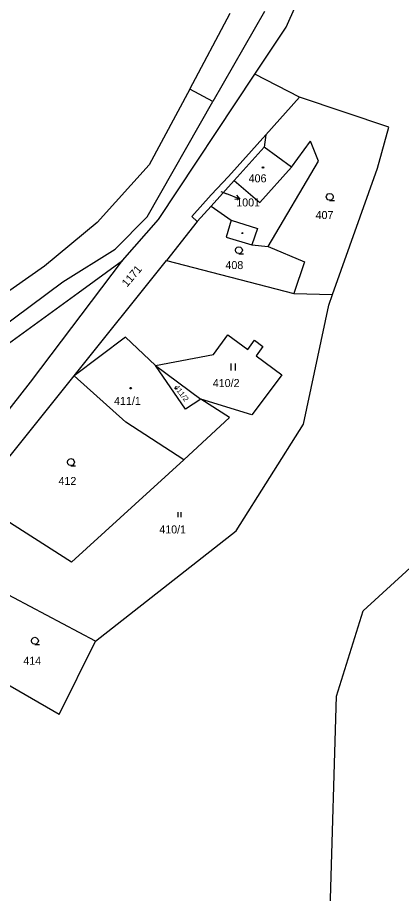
# Model space of a CAD drawing. Extents: x -812394 to -807601, y -1013097 to -1009266.
# Drawn here: x -810837.2 to -810755.5, y -1011724.6 to -1011538.5 of the extents above; entities that cross this region are included whole.
import ezdxf

# ---------------------------------------------------------------- set-up
doc = ezdxf.new("R2010")
doc.units = 0
for name, color, linetype in [('Default', 7, 'Continuous'), ('KN_HRANICE', 7, 'Continuous'), ('KN_KULTURY', 7, 'Continuous'), ('KN_PARCELY', 7, 'Continuous'), ('KN_SLUCKY', 7, 'Continuous')]:
    doc.layers.add(name, color=color, linetype=linetype)

# ---------------------------------------------------------------- blocks, each defined once
blk = doc.blocks.new('10292')
at = {"layer": 'Default'}
blk.add_line((0, 3), (0, 0), dxfattribs=at)
blk.add_lwpolyline([(-0.5, 2), (0, 3), (0.5, 2)], dxfattribs=at)
blk = doc.blocks.new('304')
at = {"layer": 'Default'}
blk.add_lwpolyline([(0, 0), (-0.38, 0.1), (-0.65, 0.37), (-0.75, 0.74), (-0.65, 1.11), (-0.38, 1.38), (-0.01, 1.48), (0.36, 1.38), (0.63, 1.11), (0.73, 0.73), (0.63, 0.35), (0.36, 0.08), (-0.02, -0.02), (0.98, -0.02)], dxfattribs=at)
blk = doc.blocks.new('306')
at = {"layer": 'Default'}
for p, q in [((-0.5, 1.5), (-0.5, 0)), ((0.5, 0), (0.5, 1.5))]:
    blk.add_line(p, q, dxfattribs=at)
blk = doc.blocks.new('NAHRADNI_SYMBOL')
at = {"layer": 'Default'}
blk.add_lwpolyline([(0.09, 0.15), (0.18, 0), (0.09, -0.15), (-0.09, -0.15), (-0.18, 0), (-0.09, 0.15), (0.09, 0.15)], dxfattribs=at)
blk = doc.blocks.new('402')
at = {"layer": 'Default'}
blk.add_lwpolyline([(0.09, 0.15), (0.18, 0), (0.09, -0.15), (-0.09, -0.15), (-0.18, 0), (-0.09, 0.15), (0.09, 0.15)], dxfattribs=at)

msp = doc.modelspace()

# ---------------------------------------------------------------- linework, layer by layer
at = {"layer": 'KN_HRANICE'}
for p, q in [((-810784.63, -1011537.23), (-810795.57, -1011556.36)), ((-810800.53, -1011553.7), (-810791.91, -1011537.6)), ((-810777.16, -1011555.46), (-810786.65, -1011550.55)), ((-810800.53, -1011553.7), (-810809.15, -1011569.79)), ((-810795.57, -1011556.36), (-810800.53, -1011553.7)), ((-810777.16, -1011555.46), (-810784.33, -1011563.43)), ((-810758.13, -1011561.79), (-810777.16, -1011555.46)), ((-810809.59, -1011580.88), (-810795.57, -1011556.36)), ((-810760.56, -1011570.51), (-810758.13, -1011561.79)), ((-810784.33, -1011563.43), (-810784.69, -1011566.07)), ((-810778.84, -1011570.27), (-810774.83, -1011564.74)), ((-810773.09, -1011568.99), (-810774.83, -1011564.74)), ((-810784.69, -1011566.07), (-810791.05, -1011573.12)), ((-810778.84, -1011570.27), (-810784.69, -1011566.07)), ((-810809.15, -1011569.79), (-810820.21, -1011582.08)), ((-810783.83, -1011587.16), (-810773.09, -1011568.99)), ((-810770.11, -1011597.34), (-810760.56, -1011570.51)), ((-810791.05, -1011573.12), (-810795.98, -1011578.6)), ((-810795.98, -1011578.6), (-810798.92, -1011581.87)), ((-810795.98, -1011578.6), (-810791.67, -1011581.54)), ((-810816.35, -1011587.73), (-810809.59, -1011580.88)), ((-810798.92, -1011581.87), (-810805.49, -1011590.1)), ((-810791.67, -1011581.54), (-810792.74, -1011585.15)), ((-810820.21, -1011582.08), (-810831.4, -1011591.35)), ((-810792.74, -1011585.15), (-810787.3, -1011586.77)), ((-810787.3, -1011586.77), (-810783.83, -1011587.16)), ((-810783.83, -1011587.16), (-810776.13, -1011590.43)), ((-810827.53, -1011594.64), (-810816.35, -1011587.73)), ((-810825.11, -1011614.6), (-810805.49, -1011590.1)), ((-810824.29, -1011596.97), (-810814.84, -1011590.15)), ((-810805.49, -1011590.1), (-810778.39, -1011597.16)), ((-810776.13, -1011590.43), (-810778.39, -1011597.16)), ((-810831.4, -1011591.35), (-810863.67, -1011613.78)), ((-810851.23, -1011612.3), (-810827.53, -1011594.64)), ((-810849.63, -1011615.36), (-810824.29, -1011596.97)), ((-810778.39, -1011597.16), (-810770.11, -1011597.34)), ((-810770.92, -1011599.62), (-810770.11, -1011597.34)), ((-810776.29, -1011624.93), (-810770.92, -1011599.62)), ((-810795.48, -1011610.09), (-810792.38, -1011605.92)), ((-810792.38, -1011605.92), (-810788.17, -1011609.04)), ((-810814.15, -1011606.38), (-810825.11, -1011614.6)), ((-810807.8, -1011612.43), (-810814.15, -1011606.38)), ((-810788.17, -1011609.04), (-810786.71, -1011607.08)), ((-810786.71, -1011607.08), (-810784.94, -1011608.39)), ((-810784.94, -1011608.39), (-810786.4, -1011610.35)), ((-810807.8, -1011612.43), (-810795.48, -1011610.09)), ((-810786.4, -1011610.35), (-810780.94, -1011614.41)), ((-810801.41, -1011621.68), (-810807.8, -1011612.43)), ((-810807.8, -1011612.43), (-810798.15, -1011619.6)), ((-810840.43, -1011633.72), (-810825.11, -1011614.6)), ((-810814.09, -1011624.47), (-810825.11, -1011614.6)), ((-810780.94, -1011614.41), (-810784.04, -1011618.58)), ((-810784.04, -1011618.58), (-810787.28, -1011622.93)), ((-810798.15, -1011619.6), (-810801.41, -1011621.68)), ((-810787.28, -1011622.93), (-810798.15, -1011619.6)), ((-810792.08, -1011623.48), (-810798.15, -1011619.6)), ((-810801.74, -1011632.47), (-810814.09, -1011624.47)), ((-810792.08, -1011623.48), (-810801.74, -1011632.47)), ((-810790.62, -1011647.55), (-810776.29, -1011624.93)), ((-810801.74, -1011632.47), (-810825.68, -1011654.24)), ((-810825.68, -1011654.24), (-810846.16, -1011641.14)), ((-810820.6, -1011671.03), (-810790.62, -1011647.55)), ((-810763.59, -1011664.59), (-810749.89, -1011651.97)), ((-810820.6, -1011671.03), (-810845.13, -1011657.96)), ((-810769.26, -1011682.72), (-810763.59, -1011664.59)), ((-810828.27, -1011686.59), (-810820.6, -1011671.03)), ((-810828.27, -1011686.59), (-810844.35, -1011677.34)), ((-810770.67, -1011728.15), (-810769.26, -1011682.72))]:
    msp.add_line(p, q, dxfattribs=at)
for points in [[(-810786.65, -1011550.55), (-810780.03, -1011540.57), (-810775.59, -1011530.62), (-810772.3, -1011515.42), (-810772.06, -1011507.46), (-810775.87, -1011475.3)], [(-810814.84, -1011590.15), (-810807.13, -1011581.45), (-810786.65, -1011550.55)], [(-810784.33, -1011563.43), (-810792.3, -1011572.28), (-810795.98, -1011576.16), (-810800.04, -1011580.78), (-810798.92, -1011581.87)], [(-810845.57, -1011630.24), (-810834.41, -1011616.01), (-810814.84, -1011590.15)]]:
    msp.add_lwpolyline(points, dxfattribs=at)
at = {"layer": 'KN_PARCELY'}
msp.add_line((-810793.9, -1011575.45), (-810792.61, -1011575.98), dxfattribs=at)
at = {"layer": 'KN_SLUCKY'}
for p, q in [((-810785.63, -1011577.82), (-810778.84, -1011570.27)), ((-810791.05, -1011573.12), (-810785.63, -1011577.82)), ((-810791.67, -1011581.54), (-810786.13, -1011583.33)), ((-810786.13, -1011583.33), (-810787.3, -1011586.77))]:
    msp.add_line(p, q, dxfattribs=at)

# ---------------------------------------------------------------- block references
at = {"layer": 'KN_KULTURY'}
for name, p in [('402', (-810784.91, -1011570.35)), ('304', (-810770.73, -1011577.34)), ('304', (-810790.05, -1011588.67)), ('306', (-810791.28, -1011613.49)), ('NAHRADNI_SYMBOL', (-810813.1, -1011617.23)), ('304', (-810825.78, -1011633.7)), ('304', (-810833.45, -1011671.66))]:
    msp.add_blockref(name, p, dxfattribs=at)
at = {"layer": 'KN_KULTURY', "xscale": 0.67, "yscale": 0.67}
for name, p in [('402', (-810789.32, -1011584.29)), ('NAHRADNI_SYMBOL', (-810803.56, -1011617.27)), ('306', (-810802.7, -1011644.63))]:
    msp.add_blockref(name, p, dxfattribs=at)
at = {"layer": 'KN_PARCELY', "rotation": -112.25304900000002}
msp.add_blockref('10292', (-810792.61, -1011575.98), dxfattribs=at)

# ---------------------------------------------------------------- texts
at = {"layer": 'KN_PARCELY'}
for s, p in [('406', (-810787.98, -1011573.52)), ('1001', (-810790.62, -1011578.64)), ('407', (-810773.74, -1011581.32)), ('408', (-810792.92, -1011591.95)), ('410/2', (-810795.61, -1011617.01)), ('411/1', (-810816.62, -1011620.81)), ('412', (-810828.44, -1011637.81)), ('410/1', (-810807, -1011648.11)), ('414', (-810835.93, -1011676.02))]:
    msp.add_text(s, height=1.7, dxfattribs=at).set_placement(p)
for s, height, rotation, p in [('1001', 0.1, 49.217, (-810795.57, -1011577.52)), ('1171', 1.7, 49.389, (-810813.86, -1011595.89)), ('411/2', 1.14, 307.22, (-810803.92, -1011617.08))]:
    msp.add_text(s, height=height, rotation=rotation, dxfattribs=at).set_placement(p)

doc.saveas('drawing.dxf')
